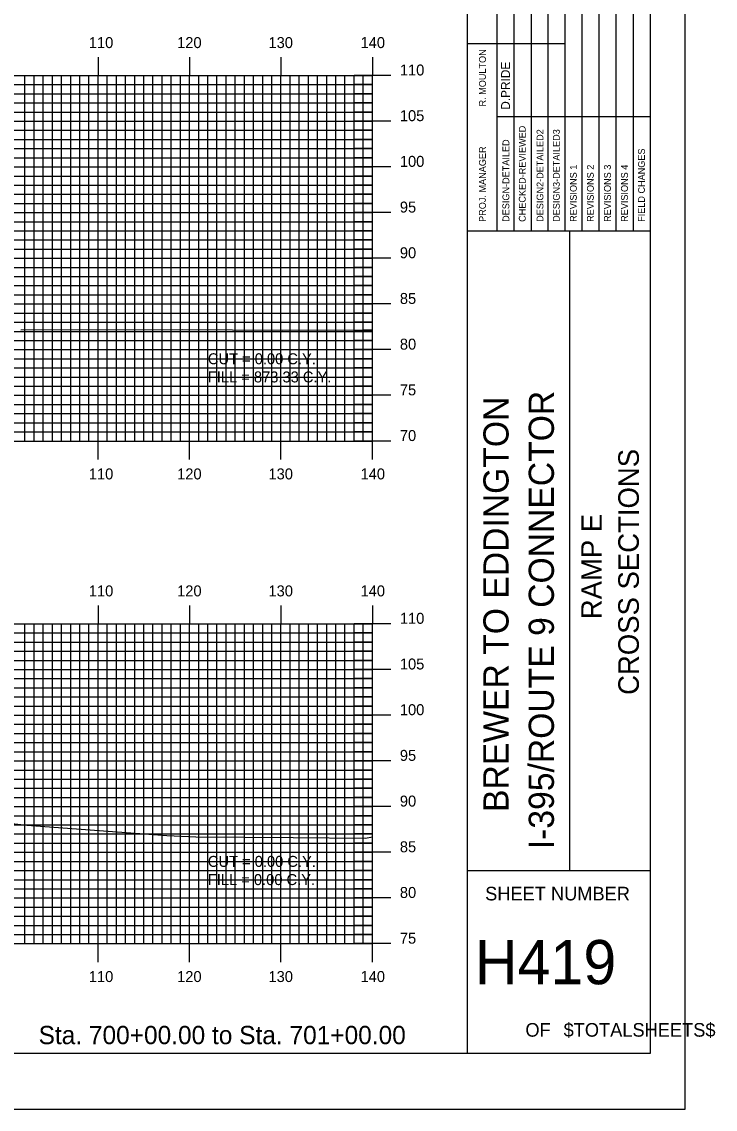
# Model space of a CAD drawing. Extents: x 852542 to 852886, y 364366 to 364586.
# Drawn here: x 852809.8 to 852885.7, y 364365.7 to 364484.7 of the extents above; entities that cross this region are included whole.
import ezdxf

# ---------------------------------------------------------------- set-up
doc = ezdxf.new("R2010")
doc.units = 0
for name, color, linetype in [('BORDER', 7, 'Continuous'), ('D_Text_Standard', 7, 'Continuous'), ('H_V ANNOTATION', 7, 'Continuous'), ('MAJOR', 7, 'Continuous'), ('MINOR', 7, 'Continuous'), ('PLOT BOUNDARY', 7, 'Continuous'), ('S_Roadway_Centerline', 7, 'Continuous')]:
    doc.layers.add(name, color=color, linetype=linetype)

msp = doc.modelspace()

# ---------------------------------------------------------------- linework, layer by layer
at = {"layer": 'BORDER'}
for p, q in [((852858.58, 364371.79), (852858.58, 364581.79)), ((852858.58, 364461.79), (852878.58, 364461.79)), ((852869.76, 364391.79), (852869.76, 364461.79)), ((852858.58, 364391.79), (852878.58, 364391.79))]:
    msp.add_line(p, q, dxfattribs=at)
msp.add_lwpolyline([(852558.58, 364371.79), (852878.58, 364371.79), (852878.58, 364581.79), (852558.58, 364581.79)], close=True, dxfattribs=at)
for points in [[(852863.67, 364461.8), (852863.67, 364496.79)], [(852865.54, 364496.79), (852865.54, 364461.8)], [(852867.4, 364461.8), (852867.4, 364496.79)], [(852869.26, 364461.8), (852869.26, 364496.79)], [(852871.13, 364461.8), (852871.13, 364496.79)], [(852872.99, 364461.8), (852872.99, 364496.79)], [(852874.85, 364461.8), (852874.85, 364496.79)], [(852876.72, 364461.8), (852876.72, 364496.79)], [(852861.81, 364461.8), (852861.81, 364495.38)], [(852858.58, 364482.29), (852861.81, 364482.29)], [(852861.81, 364482.29), (852869.26, 364482.29)], [(852861.81, 364474.29), (852878.58, 364474.29)]]:
    msp.add_lwpolyline(points, dxfattribs=at)
at = {"layer": 'MAJOR'}
for p, q in [((852818.18, 364480.79), (852818.18, 364478.79)), ((852828.18, 364480.79), (852828.18, 364478.79)), ((852838.18, 364480.79), (852838.18, 364478.79)), ((852848.18, 364480.79), (852848.18, 364478.79)), ((852568.18, 364478.79), (852848.18, 364478.79)), ((852568.18, 364478.79), (852848.18, 364478.79)), ((852818.18, 364438.79), (852818.18, 364478.79)), ((852828.18, 364438.79), (852828.18, 364478.79)), ((852838.18, 364438.79), (852838.18, 364478.79)), ((852850.18, 364478.79), (852846.17, 364478.79)), ((852848.18, 364438.79), (852848.18, 364478.79)), ((852848.18, 364438.79), (852848.18, 364478.79)), ((852568.18, 364473.79), (852848.18, 364473.79)), ((852850.18, 364473.79), (852846.17, 364473.79)), ((852568.18, 364468.79), (852848.18, 364468.79)), ((852850.18, 364468.79), (852846.17, 364468.79)), ((852568.18, 364463.79), (852848.18, 364463.79)), ((852850.18, 364463.79), (852846.17, 364463.79)), ((852568.18, 364458.79), (852848.18, 364458.79)), ((852850.18, 364458.79), (852846.17, 364458.79)), ((852568.18, 364453.79), (852848.18, 364453.79)), ((852850.18, 364453.79), (852846.17, 364453.79)), ((852568.18, 364448.79), (852848.18, 364448.79)), ((852850.18, 364448.79), (852846.17, 364448.79)), ((852568.18, 364443.79), (852848.18, 364443.79)), ((852850.18, 364443.79), (852846.17, 364443.79)), ((852568.18, 364438.79), (852848.18, 364438.79)), ((852568.18, 364438.79), (852848.18, 364438.79)), ((852818.18, 364436.78), (852818.18, 364438.79)), ((852828.18, 364436.78), (852828.18, 364438.79)), ((852838.18, 364436.78), (852838.18, 364438.79)), ((852850.18, 364438.79), (852846.17, 364438.79)), ((852848.18, 364436.78), (852848.18, 364438.79)), ((852818.18, 364420.79), (852818.18, 364418.79)), ((852828.18, 364420.79), (852828.18, 364418.79)), ((852838.18, 364420.79), (852838.18, 364418.79)), ((852848.18, 364420.79), (852848.18, 364418.79)), ((852568.18, 364418.79), (852848.18, 364418.79)), ((852568.18, 364418.79), (852848.18, 364418.79)), ((852818.18, 364383.79), (852818.18, 364418.79)), ((852828.18, 364383.79), (852828.18, 364418.79)), ((852838.18, 364383.79), (852838.18, 364418.79)), ((852850.18, 364418.79), (852846.17, 364418.79)), ((852848.18, 364383.79), (852848.18, 364418.79)), ((852848.18, 364383.79), (852848.18, 364418.79)), ((852568.18, 364413.79), (852848.18, 364413.79)), ((852850.18, 364413.79), (852846.17, 364413.79)), ((852568.18, 364408.79), (852848.18, 364408.79)), ((852850.18, 364408.79), (852846.17, 364408.79)), ((852568.18, 364403.79), (852848.18, 364403.79)), ((852850.18, 364403.79), (852846.17, 364403.79)), ((852568.18, 364398.79), (852848.18, 364398.79)), ((852850.18, 364398.79), (852846.17, 364398.79)), ((852568.18, 364393.79), (852848.18, 364393.79)), ((852850.18, 364393.79), (852846.17, 364393.79)), ((852568.18, 364388.79), (852848.18, 364388.79)), ((852850.18, 364388.79), (852846.17, 364388.79)), ((852568.18, 364383.79), (852848.18, 364383.79)), ((852568.18, 364383.79), (852848.18, 364383.79)), ((852818.18, 364381.78), (852818.18, 364383.79)), ((852828.18, 364381.78), (852828.18, 364383.79)), ((852838.18, 364381.78), (852838.18, 364383.79)), ((852850.18, 364383.79), (852846.17, 364383.79)), ((852848.18, 364381.78), (852848.18, 364383.79))]:
    msp.add_line(p, q, dxfattribs=at)
at = {"layer": 'MINOR'}
for p, q in [((852568.18, 364477.79), (852848.18, 364477.79)), ((852810.18, 364438.79), (852810.18, 364478.79)), ((852811.18, 364438.79), (852811.18, 364478.79)), ((852812.18, 364438.79), (852812.18, 364478.79)), ((852813.18, 364438.79), (852813.18, 364478.79)), ((852814.18, 364438.79), (852814.18, 364478.79)), ((852815.18, 364438.79), (852815.18, 364478.79)), ((852816.18, 364438.79), (852816.18, 364478.79)), ((852817.18, 364438.79), (852817.18, 364478.79)), ((852819.18, 364438.79), (852819.18, 364478.79)), ((852820.18, 364438.79), (852820.18, 364478.79)), ((852821.18, 364438.79), (852821.18, 364478.79)), ((852822.18, 364438.79), (852822.18, 364478.79)), ((852823.18, 364438.79), (852823.18, 364478.79)), ((852824.18, 364438.79), (852824.18, 364478.79)), ((852825.18, 364438.79), (852825.18, 364478.79)), ((852826.18, 364438.79), (852826.18, 364478.79)), ((852827.18, 364438.79), (852827.18, 364478.79)), ((852829.18, 364438.79), (852829.18, 364478.79)), ((852830.18, 364438.79), (852830.18, 364478.79)), ((852831.18, 364438.79), (852831.18, 364478.79)), ((852832.18, 364438.79), (852832.18, 364478.79)), ((852833.18, 364438.79), (852833.18, 364478.79)), ((852834.18, 364438.79), (852834.18, 364478.79)), ((852835.18, 364438.79), (852835.18, 364478.79)), ((852836.18, 364438.79), (852836.18, 364478.79)), ((852837.18, 364438.79), (852837.18, 364478.79)), ((852839.18, 364438.79), (852839.18, 364478.79)), ((852840.18, 364438.79), (852840.18, 364478.79)), ((852841.18, 364438.79), (852841.18, 364478.79)), ((852842.18, 364438.79), (852842.18, 364478.79)), ((852843.18, 364438.79), (852843.18, 364478.79)), ((852844.18, 364438.79), (852844.18, 364478.79)), ((852845.18, 364438.79), (852845.18, 364478.79)), ((852848.18, 364477.79), (852846.17, 364477.79)), ((852846.18, 364438.79), (852846.18, 364478.79)), ((852847.18, 364438.79), (852847.18, 364478.79)), ((852568.18, 364476.79), (852848.18, 364476.79)), ((852848.18, 364476.79), (852846.17, 364476.79)), ((852568.18, 364475.79), (852848.18, 364475.79)), ((852848.18, 364475.79), (852846.17, 364475.79)), ((852568.18, 364474.79), (852848.18, 364474.79)), ((852848.18, 364474.79), (852846.17, 364474.79)), ((852568.18, 364472.79), (852848.18, 364472.79)), ((852568.18, 364471.79), (852848.18, 364471.79)), ((852848.18, 364472.79), (852846.17, 364472.79)), ((852848.18, 364471.79), (852846.17, 364471.79)), ((852568.18, 364470.79), (852848.18, 364470.79)), ((852848.18, 364470.79), (852846.17, 364470.79)), ((852568.18, 364469.79), (852848.18, 364469.79)), ((852848.18, 364469.79), (852846.17, 364469.79)), ((852568.18, 364467.79), (852848.18, 364467.79)), ((852848.18, 364467.79), (852846.17, 364467.79)), ((852568.18, 364466.79), (852848.18, 364466.79)), ((852848.18, 364466.79), (852846.17, 364466.79)), ((852568.18, 364465.79), (852848.18, 364465.79)), ((852568.18, 364464.79), (852848.18, 364464.79)), ((852848.18, 364465.79), (852846.17, 364465.79)), ((852848.18, 364464.79), (852846.17, 364464.79)), ((852568.18, 364462.79), (852848.18, 364462.79)), ((852848.18, 364462.79), (852846.17, 364462.79)), ((852568.18, 364461.79), (852848.18, 364461.79)), ((852848.18, 364461.79), (852846.17, 364461.79)), ((852568.18, 364460.79), (852848.18, 364460.79)), ((852848.18, 364460.79), (852846.17, 364460.79)), ((852568.18, 364459.79), (852848.18, 364459.79)), ((852848.18, 364459.79), (852846.17, 364459.79)), ((852568.18, 364457.79), (852848.18, 364457.79)), ((852848.18, 364457.79), (852846.17, 364457.79)), ((852568.18, 364456.79), (852848.18, 364456.79)), ((852848.18, 364456.79), (852846.17, 364456.79)), ((852568.18, 364455.79), (852848.18, 364455.79)), ((852848.18, 364455.79), (852846.17, 364455.79)), ((852568.18, 364454.79), (852848.18, 364454.79)), ((852848.18, 364454.79), (852846.17, 364454.79)), ((852568.18, 364452.79), (852848.18, 364452.79)), ((852848.18, 364452.79), (852846.17, 364452.79)), ((852568.18, 364451.79), (852848.18, 364451.79)), ((852848.18, 364451.79), (852846.17, 364451.79)), ((852568.18, 364450.79), (852848.18, 364450.79)), ((852848.18, 364450.79), (852846.17, 364450.79)), ((852568.18, 364449.79), (852848.18, 364449.79)), ((852848.18, 364449.79), (852846.17, 364449.79)), ((852568.18, 364447.79), (852848.18, 364447.79)), ((852568.18, 364446.79), (852848.18, 364446.79)), ((852848.18, 364447.79), (852846.17, 364447.79)), ((852848.18, 364446.79), (852846.17, 364446.79)), ((852568.18, 364445.79), (852848.18, 364445.79)), ((852848.18, 364445.79), (852846.17, 364445.79)), ((852568.18, 364444.79), (852848.18, 364444.79)), ((852848.18, 364444.79), (852846.17, 364444.79)), ((852568.18, 364442.79), (852848.18, 364442.79)), ((852848.18, 364442.79), (852846.17, 364442.79)), ((852568.18, 364441.79), (852848.18, 364441.79)), ((852848.18, 364441.79), (852846.17, 364441.79)), ((852568.18, 364440.79), (852848.18, 364440.79)), ((852568.18, 364439.79), (852848.18, 364439.79)), ((852848.18, 364440.79), (852846.17, 364440.79)), ((852848.18, 364439.79), (852846.17, 364439.79)), ((852810.18, 364383.79), (852810.18, 364418.79)), ((852811.18, 364383.79), (852811.18, 364418.79)), ((852812.18, 364383.79), (852812.18, 364418.79)), ((852813.18, 364383.79), (852813.18, 364418.79)), ((852814.18, 364383.79), (852814.18, 364418.79)), ((852815.18, 364383.79), (852815.18, 364418.79)), ((852816.18, 364383.79), (852816.18, 364418.79)), ((852817.18, 364383.79), (852817.18, 364418.79)), ((852819.18, 364383.79), (852819.18, 364418.79)), ((852820.18, 364383.79), (852820.18, 364418.79)), ((852821.18, 364383.79), (852821.18, 364418.79)), ((852822.18, 364383.79), (852822.18, 364418.79)), ((852823.18, 364383.79), (852823.18, 364418.79)), ((852824.18, 364383.79), (852824.18, 364418.79)), ((852825.18, 364383.79), (852825.18, 364418.79)), ((852826.18, 364383.79), (852826.18, 364418.79)), ((852827.18, 364383.79), (852827.18, 364418.79)), ((852829.18, 364383.79), (852829.18, 364418.79)), ((852830.18, 364383.79), (852830.18, 364418.79)), ((852831.18, 364383.79), (852831.18, 364418.79)), ((852832.18, 364383.79), (852832.18, 364418.79)), ((852833.18, 364383.79), (852833.18, 364418.79)), ((852834.18, 364383.79), (852834.18, 364418.79)), ((852835.18, 364383.79), (852835.18, 364418.79)), ((852836.18, 364383.79), (852836.18, 364418.79)), ((852837.18, 364383.79), (852837.18, 364418.79)), ((852839.18, 364383.79), (852839.18, 364418.79)), ((852840.18, 364383.79), (852840.18, 364418.79)), ((852841.18, 364383.79), (852841.18, 364418.79)), ((852842.18, 364383.79), (852842.18, 364418.79)), ((852843.18, 364383.79), (852843.18, 364418.79)), ((852844.18, 364383.79), (852844.18, 364418.79)), ((852845.18, 364383.79), (852845.18, 364418.79)), ((852846.18, 364383.79), (852846.18, 364418.79)), ((852847.18, 364383.79), (852847.18, 364418.79)), ((852568.18, 364417.79), (852848.18, 364417.79)), ((852848.18, 364417.79), (852846.17, 364417.79)), ((852568.18, 364416.79), (852848.18, 364416.79)), ((852848.18, 364416.79), (852846.17, 364416.79)), ((852568.18, 364415.79), (852848.18, 364415.79)), ((852568.18, 364414.79), (852848.18, 364414.79)), ((852848.18, 364415.79), (852846.17, 364415.79)), ((852848.18, 364414.79), (852846.17, 364414.79)), ((852568.18, 364412.79), (852848.18, 364412.79)), ((852848.18, 364412.79), (852846.17, 364412.79)), ((852568.18, 364411.79), (852848.18, 364411.79)), ((852848.18, 364411.79), (852846.17, 364411.79)), ((852568.18, 364410.79), (852848.18, 364410.79)), ((852848.18, 364410.79), (852846.17, 364410.79)), ((852568.18, 364409.79), (852848.18, 364409.79)), ((852848.18, 364409.79), (852846.17, 364409.79)), ((852568.18, 364407.79), (852848.18, 364407.79)), ((852848.18, 364407.79), (852846.17, 364407.79)), ((852568.18, 364406.79), (852848.18, 364406.79)), ((852848.18, 364406.79), (852846.17, 364406.79)), ((852568.18, 364405.79), (852848.18, 364405.79)), ((852848.18, 364405.79), (852846.17, 364405.79)), ((852568.18, 364404.79), (852848.18, 364404.79)), ((852848.18, 364404.79), (852846.17, 364404.79)), ((852568.18, 364402.79), (852848.18, 364402.79)), ((852848.18, 364402.79), (852846.17, 364402.79)), ((852568.18, 364401.79), (852848.18, 364401.79)), ((852848.18, 364401.79), (852846.17, 364401.79)), ((852568.18, 364400.79), (852848.18, 364400.79)), ((852848.18, 364400.79), (852846.17, 364400.79)), ((852568.18, 364399.79), (852848.18, 364399.79)), ((852848.18, 364399.79), (852846.17, 364399.79)), ((852568.18, 364397.79), (852848.18, 364397.79)), ((852848.18, 364397.79), (852846.17, 364397.79)), ((852568.18, 364396.79), (852848.18, 364396.79)), ((852568.18, 364395.79), (852848.18, 364395.79)), ((852848.18, 364396.79), (852846.17, 364396.79)), ((852848.18, 364395.79), (852846.17, 364395.79)), ((852568.18, 364394.79), (852848.18, 364394.79)), ((852848.18, 364394.79), (852846.17, 364394.79)), ((852568.18, 364392.79), (852848.18, 364392.79)), ((852848.18, 364392.79), (852846.17, 364392.79)), ((852568.18, 364391.79), (852848.18, 364391.79)), ((852848.18, 364391.79), (852846.17, 364391.79)), ((852568.18, 364390.79), (852848.18, 364390.79)), ((852568.18, 364389.79), (852848.18, 364389.79)), ((852848.18, 364390.79), (852846.17, 364390.79)), ((852848.18, 364389.79), (852846.17, 364389.79)), ((852568.18, 364387.79), (852848.18, 364387.79)), ((852848.18, 364387.79), (852846.17, 364387.79)), ((852568.18, 364386.79), (852848.18, 364386.79)), ((852848.18, 364386.79), (852846.17, 364386.79)), ((852568.18, 364385.79), (852848.18, 364385.79)), ((852848.18, 364385.79), (852846.17, 364385.79)), ((852568.18, 364384.79), (852848.18, 364384.79)), ((852848.18, 364384.79), (852846.17, 364384.79))]:
    msp.add_line(p, q, dxfattribs=at)
at = {"layer": 'PLOT BOUNDARY'}
msp.add_lwpolyline([(852542.39, 364365.67), (852882.39, 364365.67), (852882.39, 364585.67), (852542.39, 364585.67)], close=True, dxfattribs=at)
at = {"layer": 'S_Roadway_Centerline'}
for points in [[(852809.73, 364450.96), (852827.36, 364451.01), (852838.37, 364450.92), (852847.13, 364450.94), (852848.18, 364450.94)], [(852688.56, 364399.68), (852700.74, 364402.23), (852709.02, 364403.3), (852713.56, 364404.2), (852730.36, 364404.93), (852731.35, 364404.92), (852732.05, 364404.93), (852753.05, 364404.11), (852763.8, 364404.1), (852768.44, 364403.63), (852771.52, 364403.34), (852784.62, 364400.76), (852790.95, 364399.49), (852792.56, 364399.19), (852795.21, 364398.76), (852804.72, 364397.39), (852810.4, 364396.75), (852825.7, 364395.64), (852828.85, 364395.47), (852839.51, 364395.39), (852847.41, 364395.34), (852848.18, 364395.46)]]:
    msp.add_lwpolyline(points, dxfattribs=at)

# ---------------------------------------------------------------- texts
at = {"layer": 'BORDER'}
for s, height, p in [('R. MOULTON', 0.745, (852860.59, 364475.4)), ('D.PRIDE', 0.969, (852863.22, 364475.04)), ('CHECKED-REVIEWED', 0.7455, (852864.94, 364462.77)), ('DESIGN2-DETAILED2', 0.7455, (852866.88, 364462.77)), ('DESIGN3-DETAILED3', 0.7455, (852868.67, 364462.77)), ('PROJ. MANAGER', 0.7455, (852860.59, 364462.77)), ('DESIGN-DETAILED', 0.7455, (852863.15, 364462.77)), ('FIELD CHANGES', 0.7455, (852877.98, 364462.77)), ('REVISIONS 1', 0.7455, (852870.53, 364462.77)), ('REVISIONS 2', 0.7455, (852872.39, 364462.77)), ('REVISIONS 3', 0.7455, (852874.26, 364462.77)), ('REVISIONS 4', 0.7455, (852876.12, 364462.77)), ('BREWER TO EDDINGTON', 2.7557, (852863.07, 364398.2)), ('I-395/ROUTE 9 CONNECTOR', 2.7557, (852868.03, 364394.12)), ('CROSS SECTIONS', 2.25, (852877.32, 364411.01)), ('RAMP E', 2.25, (852873.27, 364419.29))]:
    msp.add_text(s, height=height, rotation=90, dxfattribs=at).set_placement(p)
for s, height, p in [('SHEET NUMBER', 1.4905, (852860.51, 364388.52)), ('H419', 4.839, (852859.38, 364379.35)), ('OF', 1.491, (852864.91, 364373.61)), ('$TOTALSHEETS$', 1.4905, (852869.09, 364373.61))]:
    msp.add_text(s, height=height, dxfattribs=at).set_placement(p)
at = {"layer": 'D_Text_Standard'}
for s, p in [('CUT = 0.00 C.Y.', (852830.18, 364447.19)), ('FILL = 873.33 C.Y.', (852830.18, 364445.2)), ('CUT = 0.00 C.Y.', (852830.18, 364392.19)), ('FILL = 0.00 C.Y.', (852830.18, 364390.2))]:
    msp.add_text(s, height=1.2, dxfattribs=at).set_placement(p)
at = {"layer": 'H_V ANNOTATION'}
for s, height, p in [('110', 1.2, (852817.16, 364481.79)), ('120', 1.2, (852826.82, 364481.79)), ('130', 1.2, (852836.81, 364481.79)), ('140', 1.2, (852846.88, 364481.79)), ('110', 1.2, (852851.18, 364478.79)), ('105', 1.2, (852851.18, 364473.79)), ('100', 1.2, (852851.18, 364468.79)), ('95', 1.2, (852851.18, 364463.79)), ('90', 1.2, (852851.18, 364458.79)), ('85', 1.2, (852851.18, 364453.79)), ('80', 1.2, (852851.18, 364448.79)), ('75', 1.2, (852851.18, 364443.79)), ('70', 1.2, (852851.18, 364438.79)), ('110', 1.2, (852817.16, 364434.59)), ('120', 1.2, (852826.82, 364434.59)), ('130', 1.2, (852836.81, 364434.59)), ('140', 1.2, (852846.88, 364434.59)), ('110', 1.2, (852817.16, 364421.79)), ('120', 1.2, (852826.82, 364421.79)), ('130', 1.2, (852836.81, 364421.79)), ('140', 1.2, (852846.88, 364421.79)), ('110', 1.2, (852851.18, 364418.79)), ('105', 1.2, (852851.18, 364413.79)), ('100', 1.2, (852851.18, 364408.79)), ('95', 1.2, (852851.18, 364403.79)), ('90', 1.2, (852851.18, 364398.79)), ('85', 1.2, (852851.18, 364393.79)), ('80', 1.2, (852851.18, 364388.79)), ('75', 1.2, (852851.18, 364383.79)), ('110', 1.2, (852817.16, 364379.59)), ('120', 1.2, (852826.82, 364379.59)), ('130', 1.2, (852836.81, 364379.59)), ('140', 1.2, (852846.88, 364379.59)), ('Sta. 700+00.00 to Sta. 701+00.00', 2.0004, (852811.67, 364372.79))]:
    msp.add_text(s, height=height, dxfattribs=at).set_placement(p)

doc.saveas('drawing.dxf')
